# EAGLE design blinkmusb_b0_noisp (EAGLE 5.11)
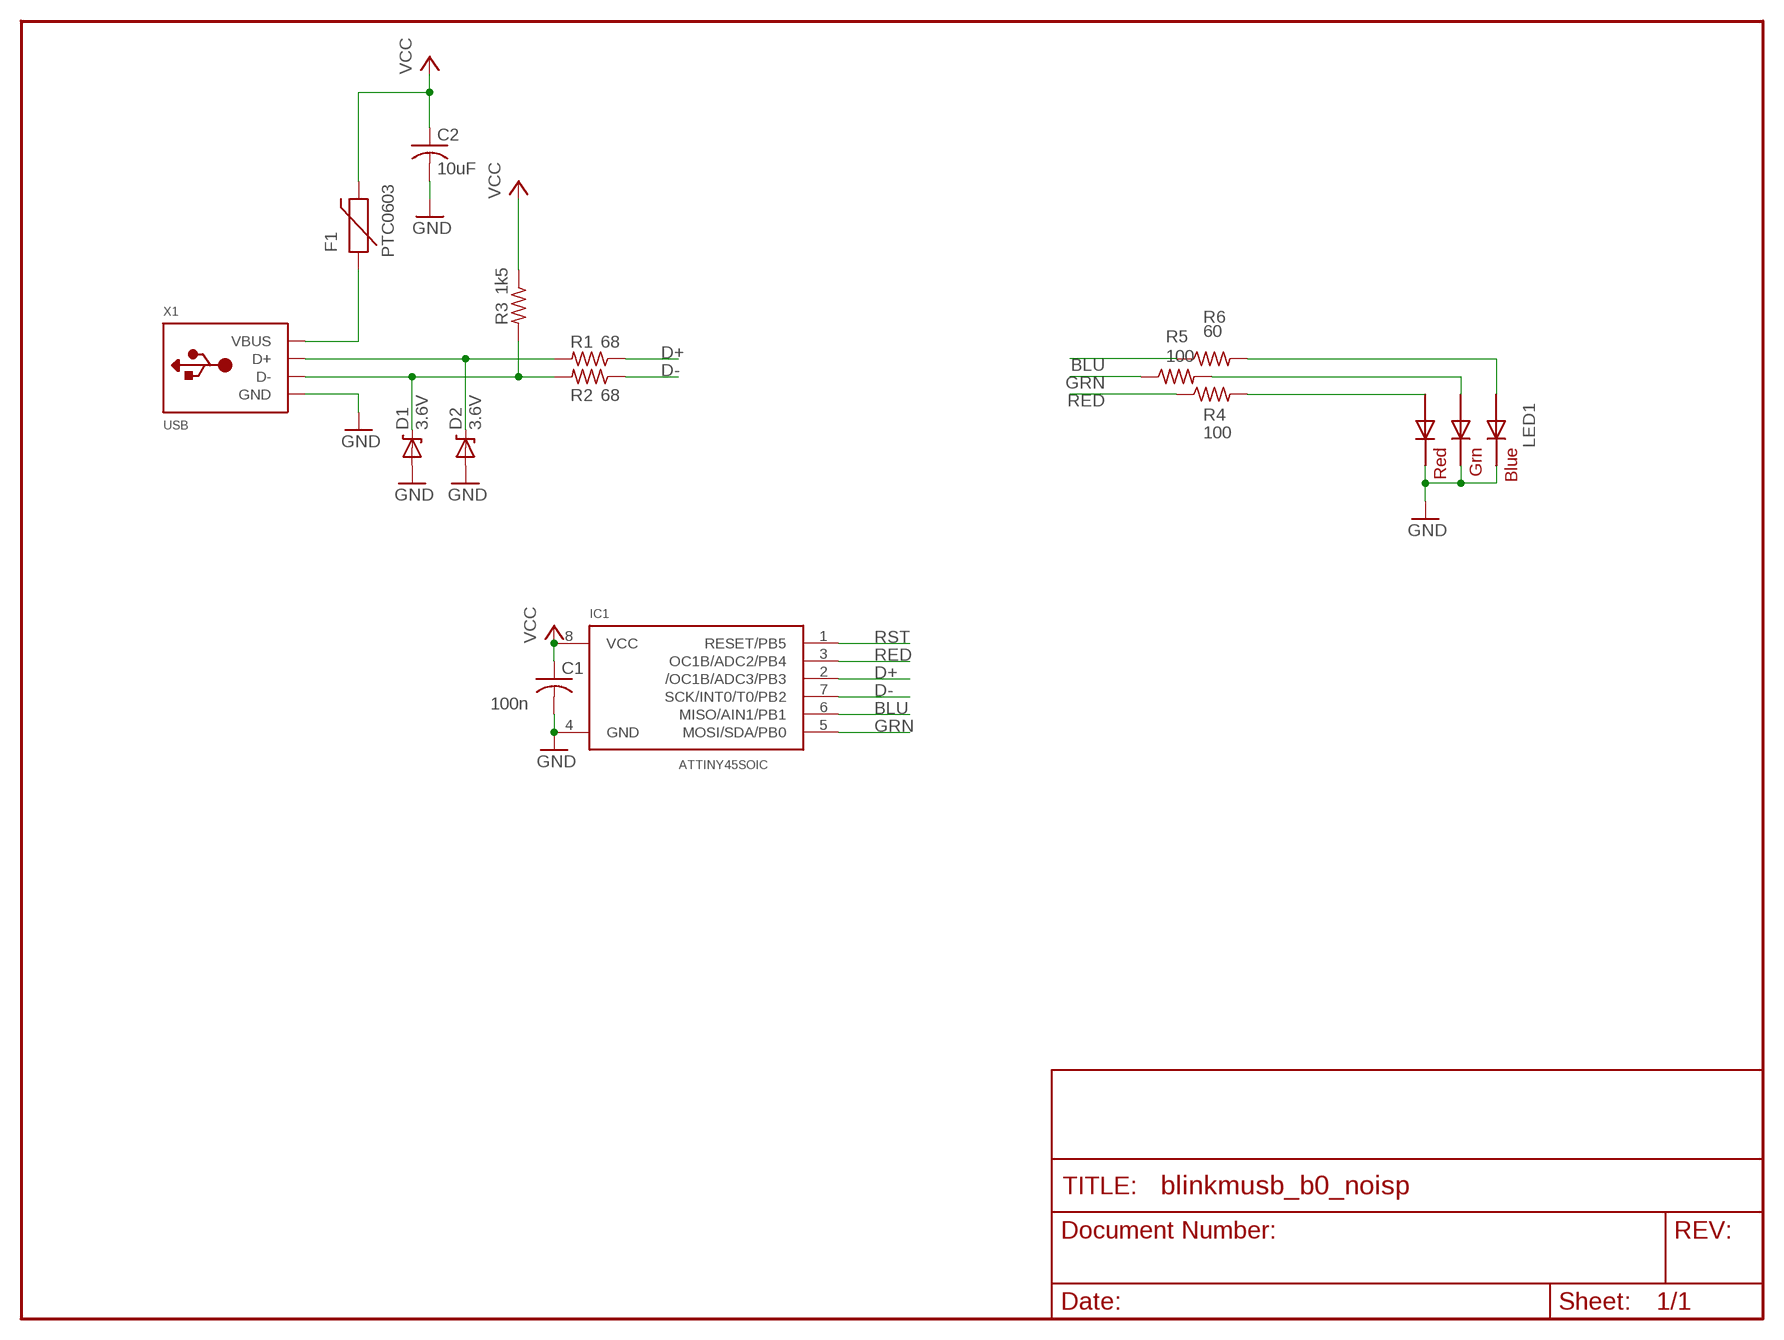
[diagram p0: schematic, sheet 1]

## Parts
C1  100n  C-USC0603  [C0603]
C2  10uF  C-USC0603  [C0603]
D1  3.6V  DIODE-ZENER-BZT52  [SOD-323]
D2  3.6V  DIODE-ZENER-BZT52  [SOD-323]
F1  PTC0603  [0603]
IC1  ATTINY45SOIC  [SO08-EIAJ]
LED1  RGBLED5050  [RGBLED5050]
R1  68  R-US_R0603  [R0603]
R2  68  R-US_R0603  [R0603]
R3  1k5  R-US_R0603  [R0603]
R4  100  R-US_R0603  [R0603]
R5  100  R-US_R0603  [R0603]
R6  60  R-US_R0603  [R0603]
X1  USB  [MOLEX-48037-1000]

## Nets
BLU: IC1.6(MISO/AIN1/PB1) R6.1
D+: IC1.2(/OC1B/ADC3/PB3) R1.1
D-: IC1.7(SCK/INT0/T0/PB2) R2.1
GND: C1.2 C2.2 D1.2(A) D2.2(A) IC1.4(GND) LED1.4(BLUE_C) LED1.5(RED_C) LED1.6(GREEN_C) X1.4(GND)
GRN: IC1.5(MOSI/SDA/PB0) R5.1
N$4: D2.1(C) R1.2 X1.3(D+)
N$5: D1.1(C) R2.2 R3.2 X1.2(D-)
N$13: F1.1 X1.1(VBUS)
RBLU: LED1.3(BLUE_A) R6.2
RED: IC1.3(OC1B/ADC2/PB4) R4.1
RGRN: LED1.1(GREEN_A) R5.2
RRED: LED1.2(RED_A) R4.2
RST: IC1.1(RESET/PB5)
VCC: C1.1 C2.1 F1.2 IC1.8(VCC) R3.1

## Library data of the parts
C1 C2 = rcl:C-US: CAPACITOR, American symbol
D1 D2 = SparkFun-20110517:DIODE-ZENER: Zener Diode
F1 = SparkFun-20110517:PTC: Resettable Fuse PTC
IC1 = todstuff:ATTINY45
LED1 = adafruit-20120122:RGBLED: For 5050 RGB LEDs, the order of the LEDs may vary from one manufacturer to another!
R1-R6 = rcl:R-US_: RESISTOR, American symbol
X1 = todstuff:USB

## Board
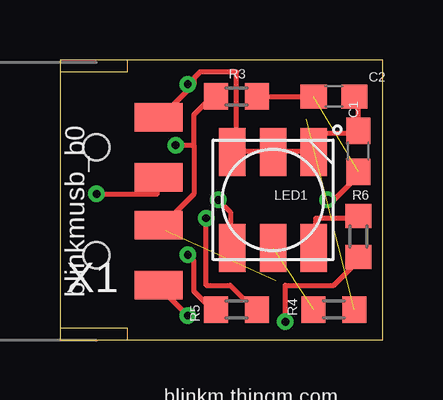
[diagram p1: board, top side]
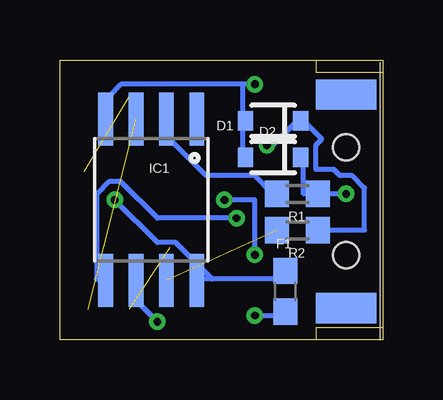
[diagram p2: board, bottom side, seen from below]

Size 13.46 x 11.68 mm. Coordinates in mm from the lower left corner, seen from the top.
Outline: 2.79,0 0,0 0,0.51
Outline: 2.79,0 13.46,0 13.46,11.68 2.79,11.68
Outline: 2.79,11.68 0,11.68 0,11.18
Outline: 0,11.18 0,0.51
Outline: 2.79,11.68 2.79,11.18 0,11.18
Outline: 0,0.51 2.79,0.51 2.79,0
Copper layers (1*16): Top 0.0356mm / dielectric 1.5011mm / Bottom 0.0356mm
Design rules "LaenPCBOrder *": minimum track width 8mil, minimum drill 13mil, track to track 6mil, track to pad 8mil, pad to pad 8mil, via to via 8mil, smd to smd 6mil, copper to edge 15mil, drill to drill 8mil, minimum pad ring 7mil, minimum via ring 7mil, stop-mask expansion 4mil, vias tented up to drill 0mil, thermal gap 10mil

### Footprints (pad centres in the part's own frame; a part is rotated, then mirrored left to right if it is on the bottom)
C0603 = smd 1.1 x 1: 1 -0.85,0; 2 0.85,0
SOD-323 = smd 0.63 x 0.83: 1 -1.15,0; 2 1.15,0
0603 = smd 1.1 x 1: 1 -0.85,0; 2 0.85,0
SO08-EIAJ = smd 0.61 x 2.21: 1 -1.905,-3.378; 2 -0.635,-3.378; 3 0.635,-3.378; 4 1.905,-3.378; 5 1.905,3.353; 6 0.635,3.353; 7 -0.635,3.353; 8 -1.905,3.353
RGBLED5050 = smd 2 x 1.1: 1 -2,1.7; 2 -2,0; 3 -2,-1.7; 4 2,-1.7; 5 2,0; 6 2,1.7
R0603 = smd 1 x 1.1: 1 -0.85,0; 2 0.85,0
MOLEX-48037-1000 = smd 2 x 1.2: 1 2.6,-3.5; 2 2.6,-1; 3 2.6,1; 4 2.6,3.5 | smd 2.54 x 1.27 bottom: P$1 0,4.45; P$2 0,-4.45 | hole 1.1: 0,2.25; 0,-2.25

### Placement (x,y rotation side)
C1  12.45,7.87 90 top
C2  11.43,10.16 0 top
D1  4.57,9.14 180 bottom
D2  4.57,7.62 180 bottom
F1  4.06,2.03 90 bottom
IC1  9.65,5.84 180 bottom
LED1  8.89,5.84 90 top
R1  3.56,6.1 0 bottom
R2  3.56,4.57 0 bottom
R3  7.37,10.16 180 top
R4  11.43,1.27 180 top
R5  7.37,1.27 180 top
R6  12.45,4.32 90 top
X1  1.52,5.79 0 top

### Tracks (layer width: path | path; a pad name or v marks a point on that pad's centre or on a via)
BLU  (via drill 0.33)
  Top 0.203: v9.4,0.76 9.4,2.29 11.43,2.29 12.45,3.3 R6.1
  Bottom 0.203: v9.4,0.76 10.16,1.52 10.16,2.29 IC1.6
D+
  Bottom 0.203: R1.1 4.57,6.1 5.33,6.86 7.37,6.86 8.89,8.38 8.89,9.14 IC1.2
D-  (1 unrouted)
GND  (via drill 0.33)
  Top 0.203: C2.2 12.45,10.16 12.45,8.89 C1.2 12.45,8.64 10.67,8.64 10.67,7.87 LED1.4 10.41,7.87 8.89,7.87 | 5.59,10.67 4.32,9.4 X1.4 | 5.59,10.67 5.59,10.92 5.84,11.18 7.37,11.18 7.37,7.87 | 7.37,7.87 LED1.6 7.37,7.87 | 7.37,7.87 8.89,7.87 | 8.89,7.87 LED1.5 8.89,7.87 | 5.59,10.67 v5.33,10.67
  Bottom 0.203: 5.84,9.14 5.84,7.62 D2.2 | 5.84,9.14 D1.2 5.84,9.14 | 5.84,10.67 5.84,9.14 | 5.84,10.67 10.92,10.67 11.43,10.16 11.43,9.4 IC1.4 | v5.33,10.67 5.84,10.67
GRN  (via drill 0.33)
  Top 0.203: v6.1,5.08 6.1,2.29 7.11,2.29 8.13,1.27 R5.1
  Bottom 0.203: v6.1,5.08 9.4,5.08 10.92,6.6 11.43,6.6 11.94,6.1 11.94,2.54 11.68,2.54 IC1.5
N$4  (via drill 0.33)
  Top 0.203: v1.52,6.1 4.06,6.1 4.06,6.6 X1.3
  Bottom 0.203: D2.1 3.3,7.62 3.3,6.1 2.79,6.1 R1.2 2.54,6.1 v1.52,6.1
N$5  (via drill 0.33)
  Top 0.203: 5.59,8.13 5.59,6.1 4.32,4.83 X1.2 | 5.59,8.13 5.59,9.4 6.35,10.16 R3.2 | v4.83,8.13 5.59,8.13
  Bottom 0.203: R2.2 2.54,4.57 0.76,4.57 0.76,6.35 1.27,6.86 1.78,6.86 2.03,7.11 2.79,7.11 2.79,8.13 2.54,8.38 3.3,9.14 D1.1 3.56,9.14 4.57,8.13 v4.83,8.13
N$13  (via drill 0.33)
  Top 0.203: v5.33,1.02 4.32,2.03 4.32,2.29 X1.1
  Bottom 0.203: v5.33,1.02 4.06,1.02 F1.1
RBLU
  Top 0.203: R6.2 12.45,5.08 10.67,5.08 10.67,4.06 LED1.3
RED  (1 unrouted)
RGRN  (via drill 0.33)
  Top 0.203: v5.33,3.56 5.59,3.3 5.59,2.03 6.35,1.27 R5.2 | v6.6,5.84 7.11,5.33 7.11,4.06 LED1.1
  Bottom 0.203: v5.33,3.56 5.33,5.84 v6.6,5.84
RRED  (1 unrouted)
VCC  (via drill 0.33)  (1 unrouted)
  Top 0.203: v11.18,5.84 11.43,5.84 12.45,6.86 C1.1 | R3.1 8.38,10.16 10.41,10.16 C2.1
  Bottom 0.203: 7.11,2.54 7.62,2.54 IC1.8 | 7.11,2.54 4.32,2.54 4.06,2.79 F1.2 | v11.18,5.84 9.4,4.06 8.64,4.06 7.11,2.54

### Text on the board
tPlace: BlinkM USB | blinkmusb_b0 | blinkm.thingm.com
